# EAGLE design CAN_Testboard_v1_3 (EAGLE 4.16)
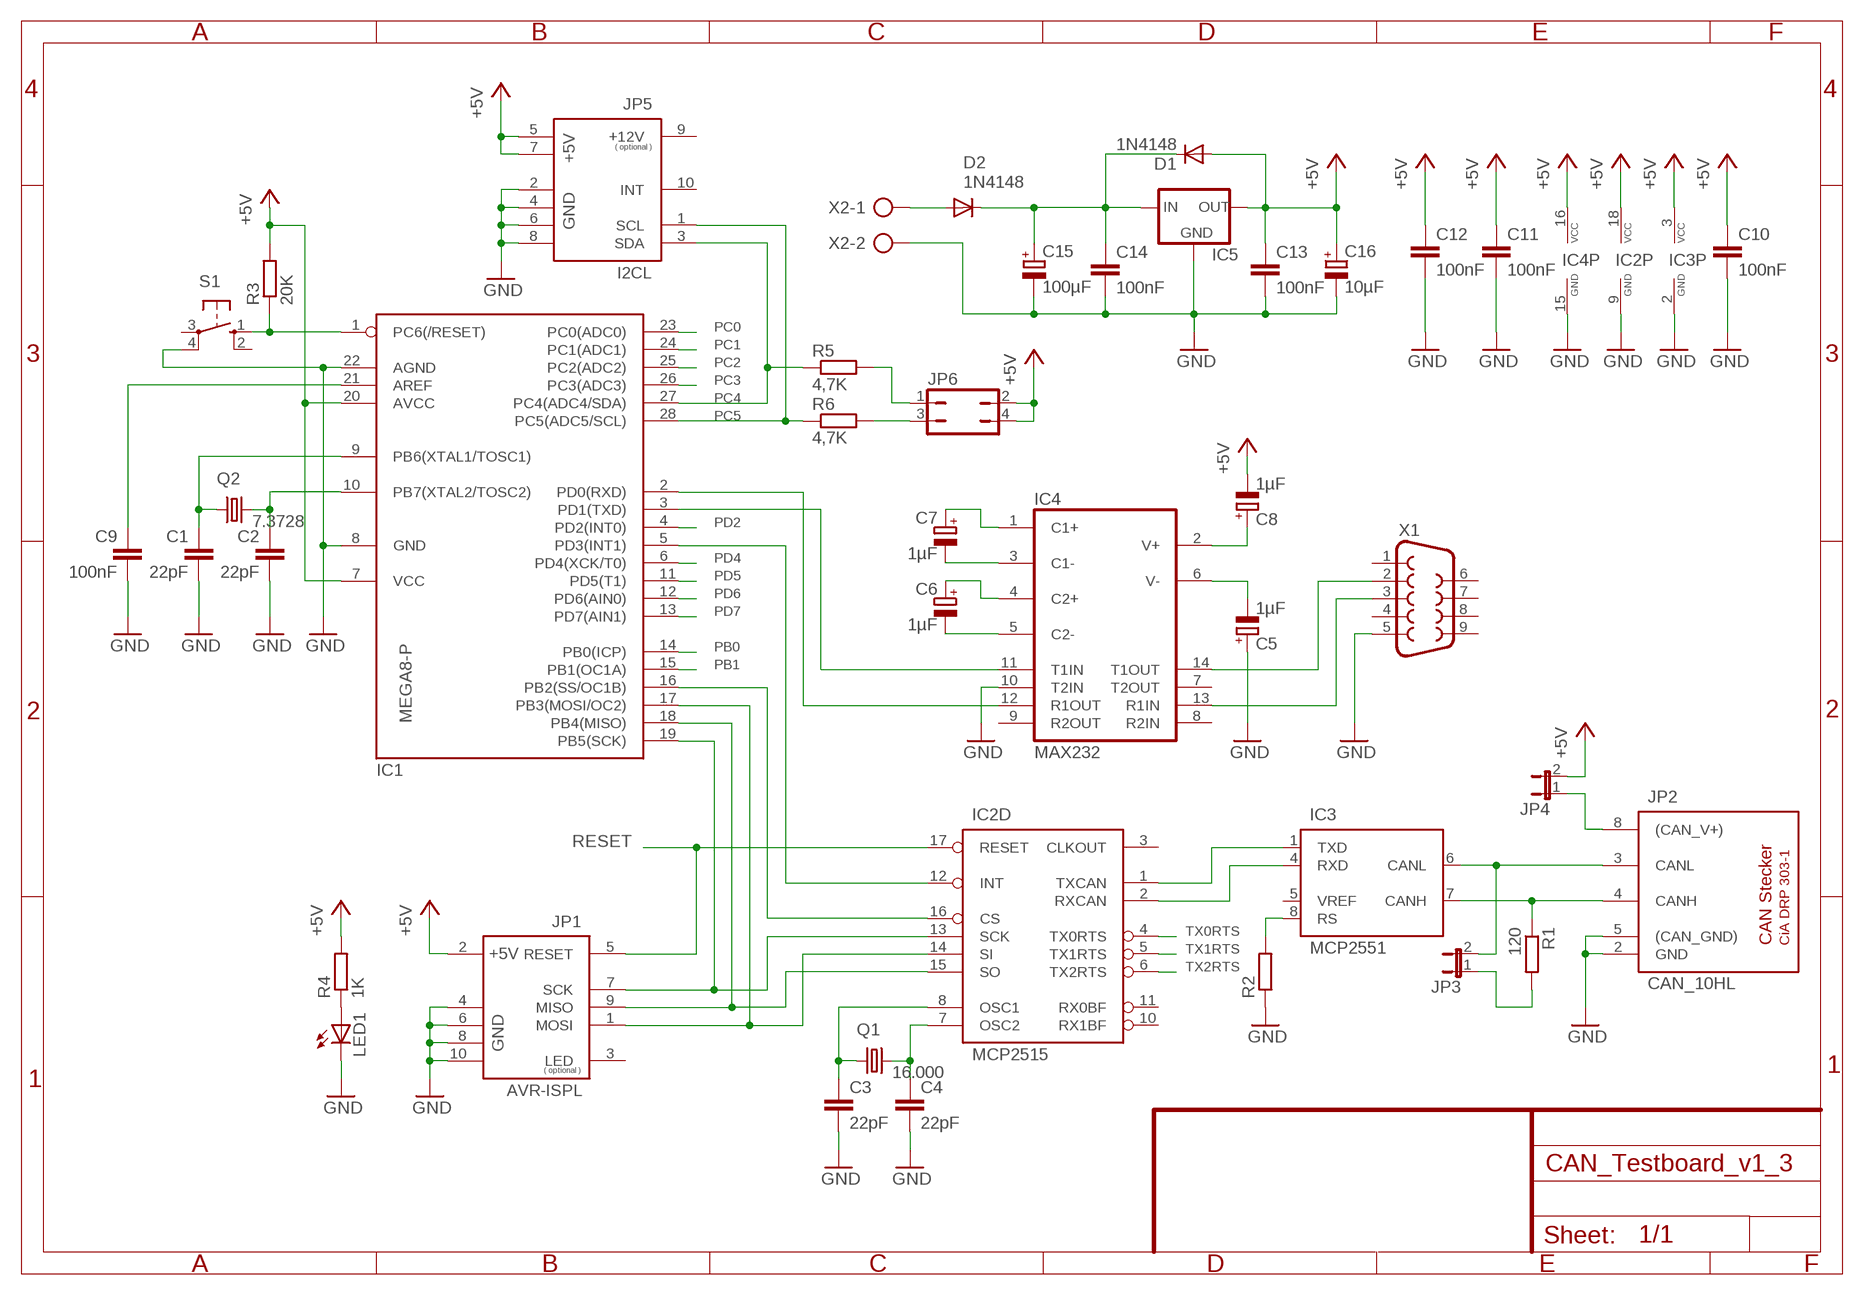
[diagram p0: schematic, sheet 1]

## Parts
C1  22pF  C-EU025-024X044  [C025-024X044]
C2  22pF  C-EU025-024X044  [C025-024X044]
C3  22pF  C-EU025-024X044  [C025-024X044]
C4  22pF  C-EU025-024X044  [C025-024X044]
C5  1µF  CPOL-EUE2.5-5  [E2,5-5]
C6  1µF  CPOL-EUE2.5-5  [E2,5-5]
C7  1µF  CPOL-EUE2.5-5  [E2,5-5]
C8  1µF  CPOL-EUE2.5-5  [E2,5-5]
C9  100nF  C-EU025-024X044  [C025-024X044]
C10  100nF  C-EU025-024X044  [C025-024X044]
C11  100nF  C-EU025-024X044  [C025-024X044]
C12  100nF  C-EU025-024X044  [C025-024X044]
C13  100nF  C-EU025-024X044  [C025-024X044]
C14  100nF  C-EU025-024X044  [C025-024X044]
C15  100µF  CPOL-EUE2.5-7  [E2,5-7]
C16  10µF  CPOL-EUE2.5-5  [E2,5-5]
D1  1N4148  [DO35-10]
D2  1N4148  [DO35-10]
IC1  MEGA8-P  [DIL28-3]
IC2  MCP2515  MCP2515P  [DIL18]
IC3  MCP2551  PCA82C250  [DIL08]
IC4  MAX232  [DIL16]
IC5  78XXL  [78XXL]
JP1  AVR-ISPL  [ML10L]
JP2  CAN_10HL  [ML10L]
JP3  JP1E  [JP1]
JP4  JP1E  [JP1]
JP5  I2CL  [ML10L]
JP6  JP2Q  [JP2Q]
LED1  LED3MM  [LED3MM]
Q1  16.000  CRYTALHC49U-V  [HC49U-V]
Q2  7.3728  CRYTALHC49U-V  [HC49U-V]
R1  120  R-EU_0207/7  [0207/7]
R2  R-EU_0207/7  [0207/7]
R3  20K  R-EU_0207/7  [0207/7]
R4  1K  R-EU_0207/10  [0207/10]
R5  4,7K  R-EU_0207/7  [0207/7]
R6  4,7K  R-EU_0207/7  [0207/7]
S1  10-XX  [B3F-10XX]
X1  F09HP  [F09HP]
X2  AK500/2  [AK500/2]

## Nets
+5V: C8.- C10.1 C11.1 C12.1 C13.1 C16.+ D1.A IC1.7(VCC) IC1.20(AVCC) IC2.18(P:VCC) IC3.3(VCC) IC4.16(VCC) IC5.OUT JP1.2(+5V) JP4.2 JP5.5(+5V) JP5.7(+5V) JP6.2 JP6.4 R3.2 R4.2
CAN_CS: IC1.16(PB2(SS/OC1B)) IC2.16(D:CS)
CAN_INT: IC1.5(PD3(INT1)) IC2.12(D:INT)
GND: C1.2 C2.2 C3.2 C4.2 C5.+ C9.2 C10.2 C11.2 C12.2 C13.2 C14.2 C15.- C16.- IC1.8(GND) IC1.22(AGND) IC2.9(P:GND) IC3.2(GND) IC4.10(T2IN) IC4.15(GND) IC5.GND JP1.4(GND) JP1.6(GND) JP1.8(GND) JP1.10(GND) JP2.2(GND) JP2.5((CAN_GND)) JP5.2(GND) JP5.4(GND) JP5.6(GND) JP5.8(GND) LED1.K(C) R2.1 S1.4(P1) X1.5 X2.2
MISO: IC1.18(PB4(MISO)) IC2.15(D:SO) JP1.9(MISO)
MOSI: IC1.17(PB3(MOSI/OC2)) IC2.14(D:SI) JP1.1(MOSI)
N$1: C6.- IC4.5(C2-)
N$2: C6.+ IC4.4(C2+)
N$3: C7.- IC4.3(C1-)
N$4: C8.+ IC4.2(V+)
N$5: C5.- IC4.6(V-)
N$8: C7.+ IC4.1(C1+)
N$9: C4.1 IC2.7(D:OSC2) Q1.2
N$10: IC2.1(D:TXCAN) IC3.1(TXD)
N$11: IC2.2(D:RXCAN) IC3.4(RXD)
N$12: C3.1 IC2.8(D:OSC1) Q1.1
N$13: C9.1 IC1.21(AREF)
N$17: C2.1 IC1.10(PB7(XTAL2/TOSC2)) Q2.2
N$18: C1.1 IC1.9(PB6(XTAL1/TOSC1)) Q2.1
N$21: IC3.8(RS) R2.2
N$22: IC3.6(CANL) JP2.3(CANL) JP3.2
N$23: IC3.7(CANH) JP2.4(CANH) R1.1
N$24: JP2.8((CAN_V+)) JP4.1
N$25: JP3.1 R1.2
N$44: LED1.A R4.1
N$48: C14.1 C15.+ D1.C D2.C IC5.IN
N$51: D2.A X2.1
N$52: JP6.3 R6.2
N$53: JP6.1 R5.2
PB0: IC1.14(PB0(ICP))
PB1: IC1.15(PB1(OC1A))
PC0: IC1.23(PC0(ADC0))
PC1: IC1.24(PC1(ADC1))
PC2: IC1.25(PC2(ADC2))
PC3: IC1.26(PC3(ADC3))
PC4: IC1.27(PC4(ADC4/SDA)) JP5.3(SDA) R5.1
PC5: IC1.28(PC5(ADC5/SCL)) JP5.1(SCL) R6.1
PD2: IC1.4(PD2(INT0))
PD4: IC1.6(PD4(XCK/T0))
PD5: IC1.11(PD5(T1))
PD6: IC1.12(PD6(AIN0))
PD7: IC1.13(PD7(AIN1))
R_IN: IC4.13(R1IN) X1.3
RESET: IC1.1(PC6(/RESET)) IC2.17(D:RESET) JP1.5(RESET) R3.1 S1.1(S)
RXD: IC1.2(PD0(RXD)) IC4.12(R1OUT)
SCK: IC1.19(PB5(SCK)) IC2.13(D:SCK) JP1.7(SCK)
T_OUT: IC4.14(T1OUT) X1.2
TX0RTS: IC2.4(D:TX0RTS)
TX1RTS: IC2.5(D:TX1RTS)
TX2RTS: IC2.6(D:TX2RTS)
TXD: IC1.3(PD1(TXD)) IC4.11(T1IN)
Unconnected: IC2.3(D:CLKOUT) IC2.10(D:RX1BF) IC2.11(D:RX0BF) IC3.5(VREF) IC4.7(T2OUT) IC4.8(R2IN) IC4.9(R2OUT) JP1.3(LED) JP5.9(+12V) JP5.10(INT) S1.2(S1) S1.3(P) X1.1 X1.4 X1.6 X1.7 X1.8 X1.9

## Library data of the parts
C1-C4 C9-C14 = rcl:C-EU: CAPACITOR, European symbol
C5-C8 C15 C16 = rcl:CPOL-EU: POLARIZED CAPACITOR, European symbol
D1 D2 = diode:1N4148: DIODE
IC1 = avr:MEGA8-P: MICROCONTROLLER 8 Kbytes FLASH 1 kbytes SRAM 512 bytes EEPROM USART 4-channel 10 bit ADC 2-channel 8 bit ADC
IC2 = andereBauteile:MCP2515: MC2515 Stand-Alone CAN Controller With SPI Interface
IC3 = andereBauteile:PCA82C250: PCA82C250 CAN Bustreiber
IC4 = maxim:MAX232: RS232 TRANSEIVER
IC5 = v-reg:78XXL: VOLTAGE REGULATOR
JP1 = roboternetz-definitionen:AVR-ISP: ISP ( In System Programming ) Stecker für AVRs Über diesen Anschluß kann ein AVR mit einem Standard ISP-Kabel direkt an einen Parallelport des PC´s angeschlossen und programmiert werden. Die Belegung des ISP-Anschlusses ist zu dem weit verbreitetet STK200 Programmier Dongle kompatibel. Ein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
JP2 = roboternetz-definitionen:CAN_: CAN Stecker nach CiA DRP 303-1
JP3 JP4 = jumper:JP1E: JUMPER
JP5 = roboternetz-definitionen:I2C: I2C Bus Stecker Ein universeller serieller Bus für Erweiterungen. Der Bus hat den Vorteil das zwei Leitungen ausreichen und keine festen Taktraten und Zyklen beachtet werden müssen. Zahlreichen integrierten Schaltkreise ( wie Porterweiterungen, LCD-Treiber, usw. ) nutzen diesen Bus. Am I2C-Bus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
JP6 = jumper:JP2Q: JUMPER
LED1 = led:LED: LED
Q1 Q2 = crystal:CRYTAL: CRYSTAL
R1-R6 = rcl:R-EU_: RESISTOR, European symbol
S1 = switch-omron:10-XX: OMRON SWITCH
X1 = con-subd:F09: SUB-D
X2 = con-ptr500:AK500/2: CONNECTOR

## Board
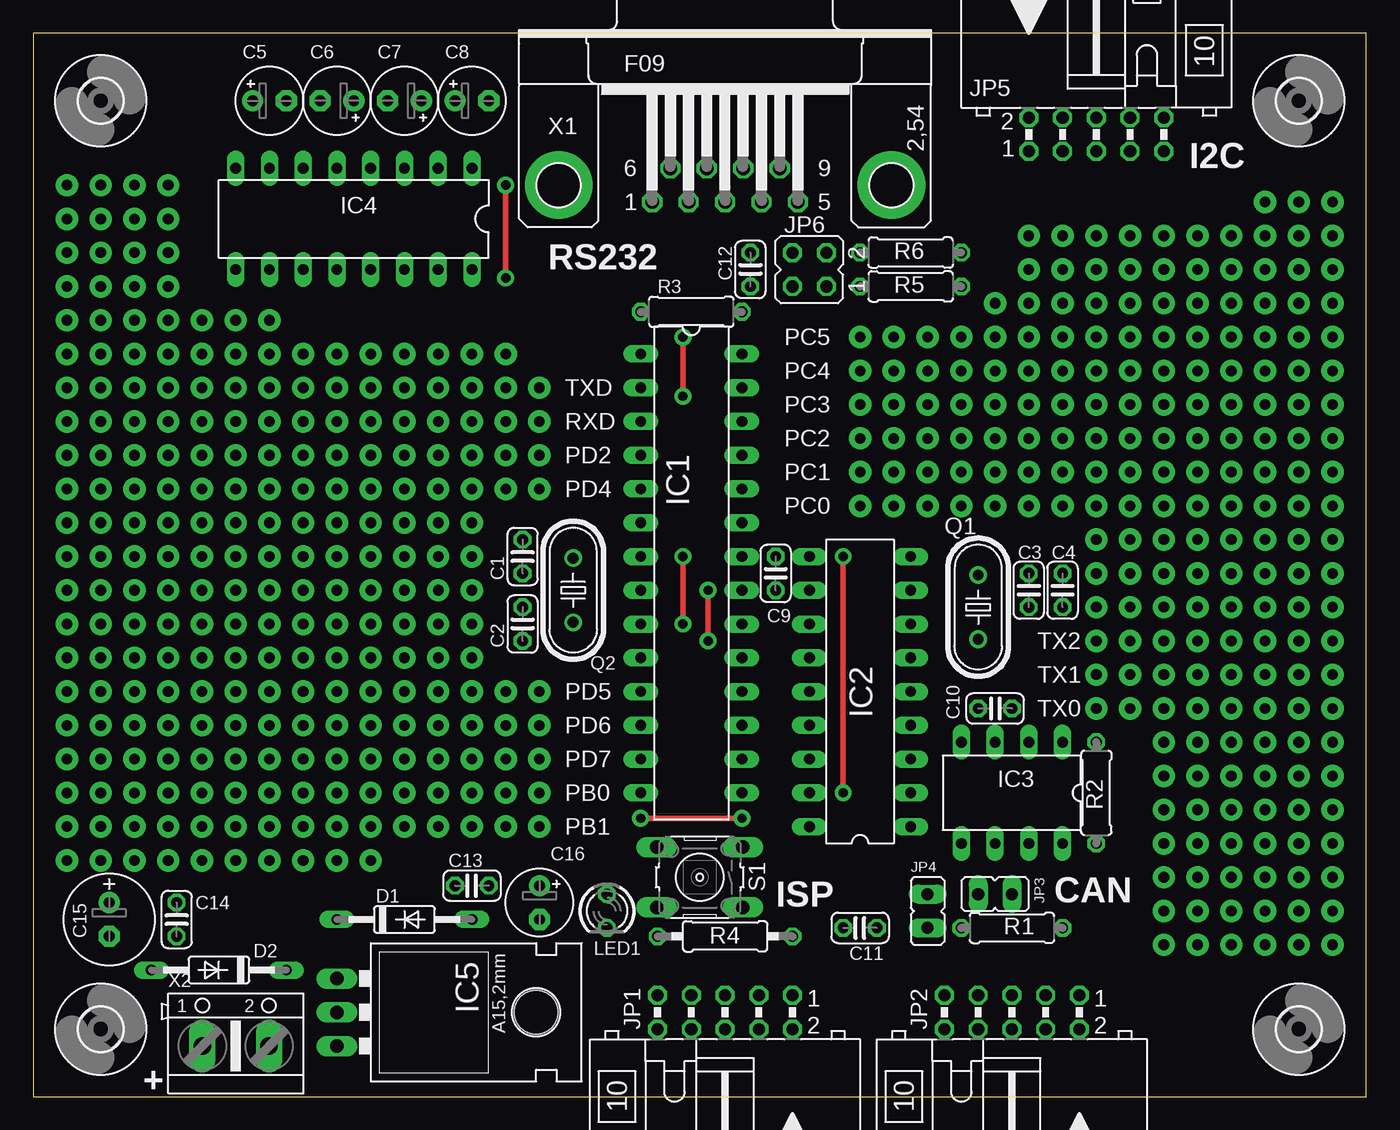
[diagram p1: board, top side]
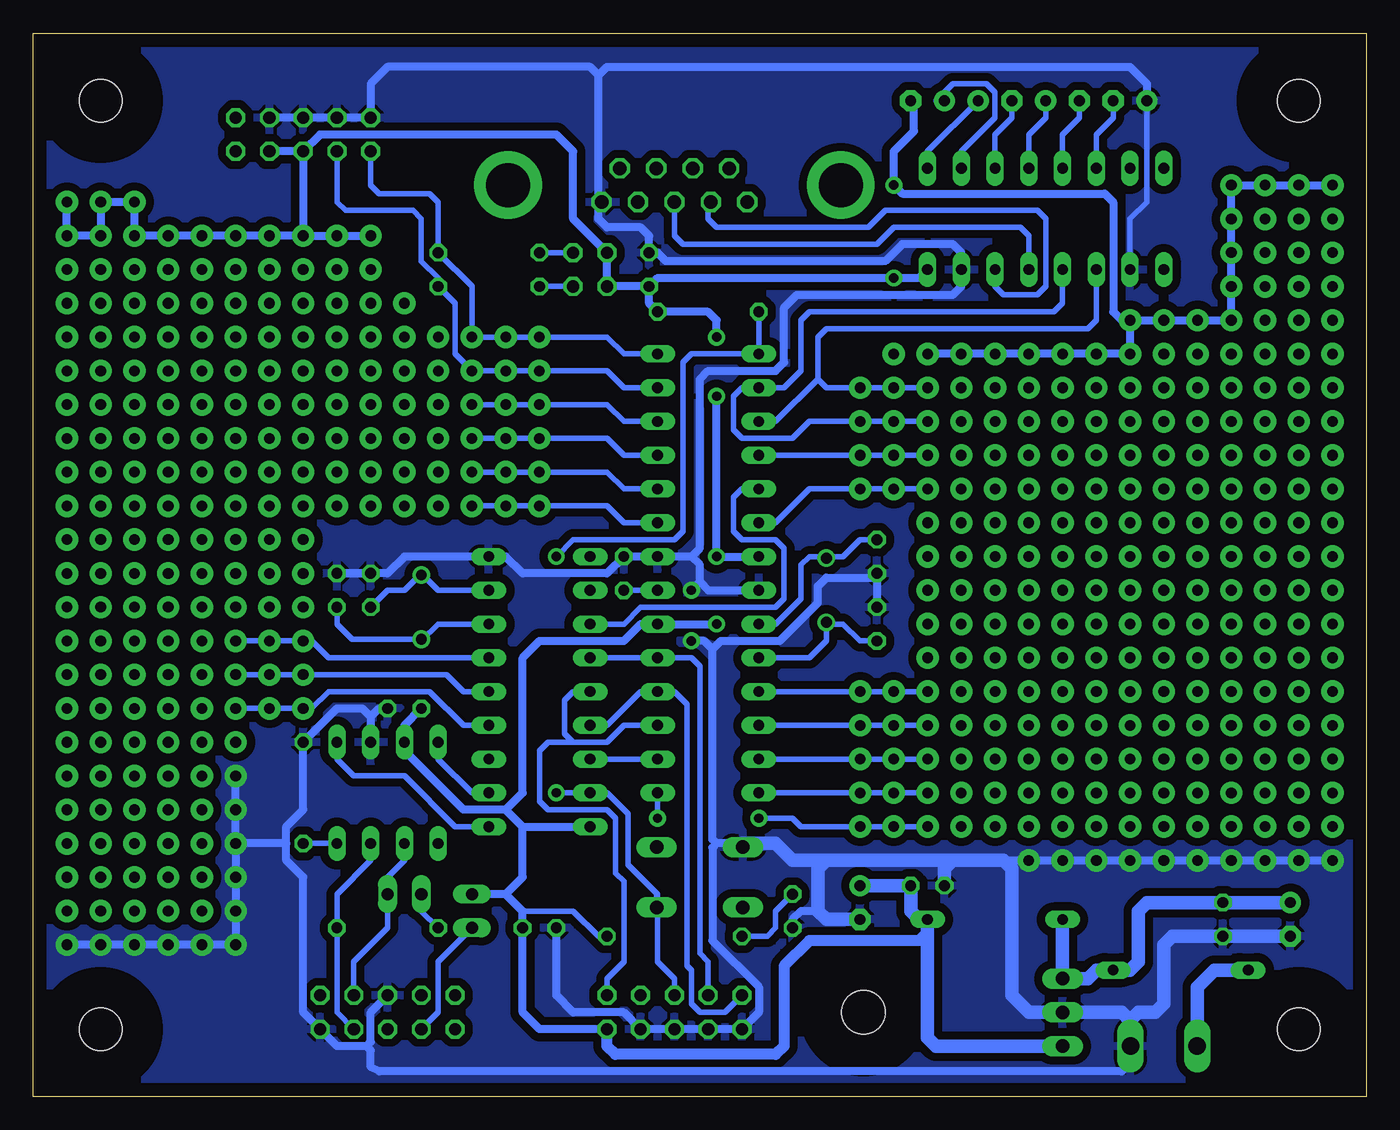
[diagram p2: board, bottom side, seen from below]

Size 100.33 x 80.01 mm. Coordinates in mm from the lower left corner, seen from the top.
Outline: 0,0 100.33,0 100.33,80.01 0,80.01 0,0
Copper layers (1*16): Top 0.035mm / dielectric 1.5mm / Bottom 0.035mm
Design rules "default": minimum track width 10mil, minimum drill 24mil, track to track 8mil, track to pad 8mil, pad to pad 8mil, via to via 8mil, smd to smd 8mil, copper to edge 40mil, drill to drill 8mil, minimum pad ring 10mil, minimum via ring 8mil, stop-mask expansion 4mil, vias tented up to drill 0mil, thermal gap 10mil

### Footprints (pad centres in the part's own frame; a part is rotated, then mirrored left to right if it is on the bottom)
C025-024X044 = drill 0.813 octagon: 1 -1.27,0; 2 1.27,0
E2,5-5 = drill 0.813 pad 1.6 round: + -1.27,0 | drill 0.813 pad 1.6 octagon: - 1.27,0
E2,5-7 = drill 0.813 pad 1.6 round: + -1.27,0 | drill 0.813 pad 1.6 octagon: - 1.27,0
DO35-10 = drill 0.813 long: A 5.08,0; C -5.08,0
DIL28-3 = drill 0.813 long: 1 -16.51,-3.81; 2 -13.97,-3.81; 3 -11.43,-3.81; 4 -8.89,-3.81; 5 -6.35,-3.81; 6 -3.81,-3.81; 7 -1.27,-3.81; 8 1.27,-3.81; 9 3.81,-3.81; 10 6.35,-3.81; 11 8.89,-3.81; 12 11.43,-3.81; 13 13.97,-3.81; 14 16.51,-3.81; 15 16.51,3.81; 16 13.97,3.81; 17 11.43,3.81; 18 8.89,3.81; 19 6.35,3.81; 20 3.81,3.81; 21 1.27,3.81; 22 -1.27,3.81; 23 -3.81,3.81; 24 -6.35,3.81; 25 -8.89,3.81; 26 -11.43,3.81; 27 -13.97,3.81; 28 -16.51,3.81
DIL18 = drill 0.813 long: 1 -10.16,-3.81; 2 -7.62,-3.81; 3 -5.08,-3.81; 4 -2.54,-3.81; 5 0,-3.81; 6 2.54,-3.81; 7 5.08,-3.81; 8 7.62,-3.81; 9 10.16,-3.81; 10 10.16,3.81; 11 7.62,3.81; 12 5.08,3.81; 13 2.54,3.81; 14 0,3.81; 15 -2.54,3.81; 16 -5.08,3.81; 17 -7.62,3.81; 18 -10.16,3.81
DIL08 = drill 0.813 long: 1 -3.81,-3.81; 2 -1.27,-3.81; 3 1.27,-3.81; 4 3.81,-3.81; 5 3.81,3.81; 6 1.27,3.81; 7 -1.27,3.81; 8 -3.81,3.81
DIL16 = drill 0.813 long: 1 -8.89,-3.81; 2 -6.35,-3.81; 3 -3.81,-3.81; 4 -1.27,-3.81; 5 1.27,-3.81; 6 3.81,-3.81; 7 6.35,-3.81; 8 8.89,-3.81; 9 8.89,3.81; 10 6.35,3.81; 11 3.81,3.81; 12 1.27,3.81; 13 -1.27,3.81; 14 -3.81,3.81; 15 -6.35,3.81; 16 -8.89,3.81
78XXL = drill 1.016 long: GND 0,-3.81; IN -2.54,-3.81; OUT 2.54,-3.81 | hole 3.302: 0,11.176
ML10L = drill 0.914 octagon: 1 -5.08,-1.27; 2 -5.08,1.27; 3 -2.54,-1.27; 4 -2.54,1.27; 5 0,-1.27; 6 0,1.27; 7 2.54,-1.27; 8 2.54,1.27; 9 5.08,-1.27; 10 5.08,1.27
JP1 = drill 0.914 long: 1 0,-1.27; 2 0,1.27
JP2Q = drill 0.914 octagon: 1 -1.27,-1.27; 2 -1.27,1.27; 3 1.27,-1.27; 4 1.27,1.27
LED3MM = drill 0.813 octagon: A -1.27,0; K 1.27,0
HC49U-V = drill 0.813 round: 1 -2.413,0; 2 2.413,0
0207/7 = drill 0.813 octagon: 1 -3.81,0; 2 3.81,0
0207/10 = drill 0.813 octagon: 1 -5.08,0; 2 5.08,0
B3F-10XX = drill 1.016 long: 1 -3.251,2.261; 2 3.251,2.261; 3 -3.251,-2.261; 4 3.251,-2.261
3,2 = hole 3.2: 0,0
F09HP = drill 1.016 octagon: 1 -5.486,-1.27; 2 -2.743,-1.27; 3 0,-1.27; 4 2.743,-1.27; 5 5.486,-1.27; 6 -4.115,1.27; 7 -1.372,1.27; 8 1.372,1.27; 9 4.115,1.27 | drill 3.302 pad 5.08 round: G1 -12.522,0; G2 12.522,0
AK500/2 = drill 1.321 long: 1 -2.515,0; 2 2.515,0

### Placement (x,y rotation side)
C1  36.83,40.64 270 top
C2  36.83,35.56 90 top
C3  74.93,38.1 90 top
C4  77.47,38.1 90 top
C5  17.78,74.93 0 top
C6  22.86,74.93 180 top
C7  27.94,74.93 180 top
C8  33.02,74.93 0 top
C9  55.88,39.37 90 top
C10  72.39,29.21 0 top
C11  62.23,12.7 180 top
C12  53.98,62.23 90 top
C13  33.02,15.88 180 top
C14  10.79,13.34 270 top
C15  5.71,13.34 270 top
C16  38.1,14.61 270 top
D1  27.94,13.34 0 top
D2  13.97,9.53 180 top
IC1  49.53,39.37 270 top
IC2  62.23,30.48 90 top
IC3  73.66,22.86 180 top
IC4  24.13,66.04 180 top
IC5  26.67,6.35 270 top
JP1  52.07,6.35 180 top
JP2  73.66,6.35 180 top
JP3  72.39,15.24 270 top
JP4  67.31,13.97 0 top
JP5  80.01,72.39 0 top
JP6  58.42,62.23 90 top
LED1  43.18,13.97 270 top
Q1  71.12,36.83 270 top
Q2  40.64,38.1 270 top
R1  73.66,12.7 180 top
R2  80.01,22.86 270 top
R3  49.53,59.05 0 top
R4  52.07,12.06 0 top
R5  66.04,60.96 180 top
R6  66.04,63.5 180 top
S1  50.16,16.51 180 top
U$1  [3,2]  5.08,5.08 0 top
U$2  [3,2]  95.25,5.08 0 top
U$3  [3,2]  95.25,74.93 0 top
U$4  [3,2]  5.08,74.93 0 top
X1  52.07,68.58 0 top
X2  15.24,3.81 0 top

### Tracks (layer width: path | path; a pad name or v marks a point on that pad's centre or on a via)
+5V  (via drill 0.7 pad 1.27, 0.8 pad 1.68)
  Top 0.406: v48.9,35.56 v48.9,40.64 | v35.56,61.59 v35.56,68.58 | v48.9,52.7 v48.9,57.15
  Bottom 0.406: R4.2 57.78,12.06 59.69,13.97 63.5,13.97
  Bottom 0.61: 64.77,21.59 67.94,21.59 72.39,26.04 IC3.3 72.39,27.94 C10.1 | 63.5,20.32 64.77,21.59 | 63.5,20.32 IC2.18 | JP1.2 62.23,5.08 63.5,6.35 C11.1 63.5,13.97 64.77,15.24 | 64.77,15.24 JP4.2 | 64.77,15.24 63.5,16.51 63.5,20.32 | v48.9,35.56 IC1.20 54.61,35.56 55.88,34.29 62.23,34.29 63.5,33.02 63.5,22.86 64.77,21.59 | IC1.7 v48.9,40.64 v48.9,52.7 | C8.- 34.04,74.68 34.04,72.64 35.56,71.12 v35.56,68.58 34.92,67.94 19.68,67.94 19.05,67.31 19.05,59.05 18.41,58.42 v17.78,58.42 | IC4.16 33.66,61.59 v35.56,61.59 53.34,61.59 C12.1 | v48.9,57.15 48.9,58.42 49.53,59.05 R3.2 53.98,59.69 C12.1 | v17.78,58.42 v15.24,58.42 v12.7,58.42 v10.16,58.42 v10.16,60.96 v10.16,63.5 v10.16,66.04 v10.16,68.58 v7.62,68.58 v5.08,68.58 v2.54,68.58 | JP5.5 JP5.7 | JP5.5 78.74,72.39 60.96,72.39 59.69,71.12 59.69,66.04 JP6.4 JP6.2 C12.1 | JP5.5 v80.01,64.77 | v80.01,64.77 v77.47,64.77 v74.93,64.77 | v80.01,64.77 v82.55,64.77 v85.09,64.77 v87.63,64.77 v90.17,64.77 v92.71,64.77 v92.71,67.31 v95.25,67.31 v95.25,64.77 v97.79,64.77 v97.79,67.31 | v17.78,58.42 v17.78,55.88 v20.32,55.88 v22.86,55.88 v25.4,55.88 v27.94,55.88 v30.48,55.88 v33.02,55.88
  Bottom 0.813: JP1.2 57.15,3.81 56.52,3.17 44.45,3.17 43.81,3.81 43.81,9.84 41.91,11.75 33.66,11.75 33.02,12.38
  Bottom 1.016: IC5.OUT 32.38,3.81 33.02,4.45 33.02,12.38 D1.A 33.66,13.34 34.29,13.97 C13.1 C16.+
CAN_CS
  Bottom 0.406: IC1.16 IC2.16
CAN_INT
  Bottom 0.406: IC2.12 55.88,35.56 54.61,36.83 44.45,36.83 43.81,37.47 43.81,41.27 44.45,41.91 46.99,41.91 47.62,42.55 47.62,45.09 46.99,45.72 IC1.5
GND  (via drill 0.7 pad 1.27, 0.8 pad 1.68)
  Top 0.406: v50.8,34.29 v50.8,38.1
  Bottom 0.406: IC4.10 17.78,66.04 16.51,67.31 C5.+ | 57.78,67.31 X1.5
  Bottom 0.61: C3.2 C4.2 73.66,39.37 72.39,40.64 IC2.9 64.77,40.64 63.5,39.37 57.15,39.37 C9.2 IC1.22 50.8,40.64 | JP2.5 74.93,6.35 74.93,4.13 75.25,3.81 | 75.25,3.81 77.47,3.81 JP2.2 80.01,6.35 80.01,16.51 81.28,17.78 81.28,19.05 | 81.28,19.05 81.28,20.32 80.01,21.59 R2.1 77.47,29.21 75.56,29.21 74.93,28.57 | IC1.8 49.53,38.1 50.16,38.73 | 50.16,38.73 50.16,40.01 50.8,40.64 | C2.2 C1.2 37.15,39.05 40.64,39.05 41.27,38.42 41.27,37.15 44.13,34.29 48.58,34.29 49.21,33.66 | C11.2 60.96,7.62 59.69,6.35 55.88,6.35 JP1.4 JP1.6 JP1.8 JP1.10 45.72,6.35 45.72,8.26 49.21,11.75 49.21,18.73 48.9,19.05 | 50.8,40.64 50.16,41.27 50.16,53.98 49.53,54.61 44.45,54.61 43.81,55.24 43.81,59.37 42.86,60.33 31.11,60.33 30.48,60.96 IC4.15 30.48,63.5 31.11,64.14 34.92,64.14 36.2,62.87 52.7,62.87 53.34,63.5 C12.2 53.98,64.77 54.61,65.41 57.15,65.41 57.78,66.04 57.78,67.31 57.78,76.83 | C5.+ 16.51,76.2 17.78,77.47 57.15,77.47 57.78,76.83 | 49.21,33.66 49.85,34.29 v50.8,34.29 | v50.8,38.1 50.16,38.73 | v97.79,11.43 v95.25,11.43 v92.71,11.43 v90.17,11.43 v87.63,11.43 v85.09,11.43 v85.09,13.97 v85.09,16.51 v85.09,19.05 | v2.54,17.78 v5.08,17.78 v7.62,17.78 v10.16,17.78 v12.7,17.78 v15.24,17.78 v17.78,17.78 v20.32,17.78 v22.86,17.78 27.3,17.78 | 57.78,76.83 58.42,77.47 73.66,77.47 74.93,76.2 JP5.2 JP5.4 JP5.6 JP5.8 | S1.4 46.91,19.13 46.99,19.05 48.9,19.05 | 49.21,33.66 49.21,19.37 48.9,19.05 | v85.09,19.05 v85.09,21.59 v85.09,24.13 | 81.28,19.05 v85.09,19.05 | 74.93,28.57 74.3,29.21 C10.2 | 74.93,28.57 IC3.2 | 75.25,3.81 74.93,3.49 74.93,2.22 74.3,1.91 18.41,1.91 17.78,2.54 17.78,3.81
  Bottom 0.61: LED1.K 43.18,13.34 42.55,13.97 41.27,13.97
  Bottom 1.016: 31.11,17.78 27.3,17.78 26.67,17.14 26.67,7.62 25.4,6.35 IC5.GND 18.41,6.35 17.78,5.71 | 31.11,17.78 40.64,17.78 | X2.2 17.78,3.81 17.78,5.71 | C15.- C14.2 14.61,12.06 15.24,11.43 15.24,6.99 15.88,6.35 17.14,6.35 17.78,5.71 | C13.2 31.75,17.14 31.11,17.78 | C16.- 40.64,13.34 41.27,13.97 41.27,17.14 40.64,17.78 | 40.64,17.78 43.18,17.78 44.45,19.05 46.99,19.05 46.91,18.97 S1.4
  other vias: 25.4,17.78
  pour Bottom (isolate 0.61): -1.27,81.28 101.6,81.28 101.6,-1.27 -1.27,-1.27
MISO
  Bottom 0.406: IC2.15 57.15,27.94 54.61,30.48 IC1.18 52.07,30.48 51.12,29.53 51.12,9.84 50.8,9.53 50.8,6.99 50.16,6.35 48.26,6.35 JP1.9
MOSI
  Bottom 0.406: JP1.1 57.15,8.89 55.88,10.16 55.88,16.19 56.52,16.83 56.52,20.95 57.15,21.59 61.59,21.59 62.23,22.23 62.23,26.04 61.59,26.67 59.69,26.67 | IC1.17 55.88,27.94 57.15,26.67 59.69,26.67 | 59.69,26.67 60.33,27.3 60.33,29.84 59.69,30.48 IC2.14
N$1
  Bottom 0.406: IC4.5 22.86,72.39 21.59,73.66 C6.-
N$2
  Bottom 0.406: IC4.4 25.4,72.39 24.13,73.66 C6.+
N$3
  Bottom 0.406: IC4.3 27.94,72.39 26.67,73.66 C7.-
N$4
  Bottom 0.406: IC4.2 30.48,71.12 27.94,73.66 27.94,75.56 28.57,76.2 31.11,76.2 32.38,74.93 C8.+
N$5
  Bottom 0.406: IC4.6 20.32,72.39 19.05,73.66 C5.-
N$8
  Bottom 0.406: IC4.1 33.02,71.12 C7.+
N$9
  Bottom 0.406: IC2.7 69.85,35.56 71.12,34.29 Q1.2 76.33,34.42 77.47,35.56 C4.1
N$10
  Bottom 0.406: IC2.1 68.58,20.32 72.39,24.13 76.2,24.13 77.47,25.4 IC3.1
N$11
  Bottom 0.406: IC3.4 69.85,25.4 67.31,22.86 IC2.2
N$12
  Bottom 0.406: IC2.8 69.85,38.1 71.12,39.37 Q1.1 71.25,39.24 72.39,38.1 73.66,38.1 C3.1
N$13
  Bottom 0.406: IC1.21 C9.1
N$17
  Bottom 0.406: 40.64,35.56 40.64,34.29 41.91,33.02 IC1.10 | C2.1 38.1,34.29 39.37,35.56 40.64,35.56 | 40.64,35.56 Q2.2
N$18
  Bottom 0.406: C1.1 38.1,41.91 39.37,40.64 40.64,40.64 | 40.64,40.64 Q2.1 | 40.64,40.64 41.91,40.64 42.55,40.01 42.55,37.47 44.45,35.56 IC1.9
N$21
  Bottom 0.406: IC3.8 R2.2
N$22
  Bottom 0.406: IC3.6 72.39,17.78 73.66,16.51 JP3.2 73.66,12.7 76.2,10.16 JP2.3
N$23
  Bottom 0.406: JP2.4 77.47,6.35 R1.1 77.47,15.24 74.93,17.78 IC3.7
N$24
  Bottom 0.406: JP2.8 69.85,6.35 69.85,10.16 JP4.1
N$25
  Bottom 0.406: R1.2 71.12,13.97 JP3.1
N$29  (via drill 0.8 pad 1.68)
  other vias: 20.32,48.26
N$30  (via drill 0.8 pad 1.68)
  other vias: 22.86,48.26
N$31  (via drill 0.8 pad 1.68)
  other vias: 25.4,48.26
N$32  (via drill 0.8 pad 1.68)
  other vias: 25.4,45.72
N$33  (via drill 0.8 pad 1.68)
  other vias: 22.86,45.72
N$34  (via drill 0.8 pad 1.68)
  other vias: 20.32,45.72
N$35  (via drill 0.8 pad 1.68)
  other vias: 20.32,43.18
N$36  (via drill 0.8 pad 1.68)
  other vias: 22.86,43.18
N$37  (via drill 0.8 pad 1.68)
  other vias: 25.4,43.18
N$38  (via drill 0.8 pad 1.68)
  other vias: 25.4,50.8
N$39  (via drill 0.8 pad 1.68)
  other vias: 22.86,50.8
N$40  (via drill 0.8 pad 1.68)
  other vias: 20.32,50.8
N$41  (via drill 0.8 pad 1.68)
  other vias: 20.32,53.34
N$42  (via drill 0.8 pad 1.68)
  other vias: 22.86,53.34
N$43  (via drill 0.8 pad 1.68)
  other vias: 25.4,53.34
N$44
  Bottom 0.406: LED1.A 44.45,13.97 44.45,12.7 45.09,12.06 R4.1
N$45  (via drill 0.8 pad 1.68)
  other vias: 77.47,62.23
N$46  (via drill 0.8 pad 1.68)
  other vias: 80.01,62.23
N$47  (via drill 0.8 pad 1.68)
  other vias: 82.55,62.23
N$48
  Bottom 1.016: D1.C IC5.IN 20.95,8.89 20.32,9.53 D2.C 17.78,9.53 17.14,10.16 17.14,13.97 16.51,14.61 C14.1 C15.+
N$49  (via drill 0.8 pad 1.68)
  other vias: 85.09,62.23
N$50  (via drill 0.8 pad 1.68)
  other vias: 74.93,62.23
N$51
  Bottom 1.016: X2.1 12.72,8.23 11.43,9.53 D2.A
N$52
  Bottom 0.406: JP6.3 R6.2
N$53
  Bottom 0.406: JP6.1 R5.2
N$54  (via drill 0.8 pad 1.68)
  other vias: 33.02,43.18
N$59  (via drill 0.8 pad 1.68)
  other vias: 27.94,48.26
N$60  (via drill 0.8 pad 1.68)
  other vias: 30.48,48.26
N$61  (via drill 0.8 pad 1.68)
  other vias: 69.85,54.61
N$62  (via drill 0.8 pad 1.68)
  other vias: 69.85,57.15
N$63  (via drill 0.8 pad 1.68)
  other vias: 30.48,45.72
N$64  (via drill 0.8 pad 1.68)
  other vias: 27.94,45.72
N$65  (via drill 0.8 pad 1.68)
  other vias: 27.94,43.18
N$66  (via drill 0.8 pad 1.68)
  other vias: 30.48,43.18
N$67  (via drill 0.8 pad 1.68)
  other vias: 85.09,26.67
N$69  (via drill 0.8 pad 1.68)
  other vias: 30.48,50.8
N$70  (via drill 0.8 pad 1.68)
  other vias: 27.94,50.8
N$71  (via drill 0.8 pad 1.68)
  other vias: 27.94,53.34
N$72  (via drill 0.8 pad 1.68)
  other vias: 30.48,53.34
N$74  (via drill 0.8 pad 1.68)
  other vias: 12.7,48.26
N$75  (via drill 0.8 pad 1.68)
  other vias: 15.24,48.26
N$76  (via drill 0.8 pad 1.68)
  other vias: 17.78,48.26
N$77  (via drill 0.8 pad 1.68)
  other vias: 17.78,45.72
N$78  (via drill 0.8 pad 1.68)
  other vias: 15.24,45.72
N$79  (via drill 0.8 pad 1.68)
  other vias: 12.7,45.72
N$80  (via drill 0.8 pad 1.68)
  other vias: 12.7,43.18
N$81  (via drill 0.8 pad 1.68)
  other vias: 15.24,43.18
N$82  (via drill 0.8 pad 1.68)
  other vias: 17.78,43.18
N$83  (via drill 0.8 pad 1.68)
  other vias: 17.78,50.8
N$84  (via drill 0.8 pad 1.68)
  other vias: 15.24,50.8
N$85  (via drill 0.8 pad 1.68)
  other vias: 12.7,50.8
N$86  (via drill 0.8 pad 1.68)
  other vias: 12.7,53.34
N$87  (via drill 0.8 pad 1.68)
  other vias: 15.24,53.34
N$88  (via drill 0.8 pad 1.68)
  other vias: 17.78,53.34
N$89  (via drill 0.8 pad 1.68)
  other vias: 5.08,48.26
N$90  (via drill 0.8 pad 1.68)
  other vias: 7.62,48.26
N$91  (via drill 0.8 pad 1.68)
  other vias: 10.16,48.26
N$92  (via drill 0.8 pad 1.68)
  other vias: 10.16,45.72
N$93  (via drill 0.8 pad 1.68)
  other vias: 7.62,45.72
N$94  (via drill 0.8 pad 1.68)
  other vias: 5.08,45.72
N$95  (via drill 0.8 pad 1.68)
  other vias: 5.08,43.18
N$96  (via drill 0.8 pad 1.68)
  other vias: 7.62,43.18
N$97  (via drill 0.8 pad 1.68)
  other vias: 10.16,43.18
N$98  (via drill 0.8 pad 1.68)
  other vias: 10.16,50.8
N$99  (via drill 0.8 pad 1.68)
  other vias: 7.62,50.8
N$100  (via drill 0.8 pad 1.68)
  other vias: 5.08,50.8
N$101  (via drill 0.8 pad 1.68)
  other vias: 5.08,53.34
N$102  (via drill 0.8 pad 1.68)
  other vias: 7.62,53.34
N$103  (via drill 0.8 pad 1.68)
  other vias: 10.16,53.34
N$104  (via drill 0.8 pad 1.68)
  other vias: 2.54,48.26
N$105  (via drill 0.8 pad 1.68)
  other vias: 2.54,45.72
N$106  (via drill 0.8 pad 1.68)
  other vias: 2.54,43.18
N$107  (via drill 0.8 pad 1.68)
  other vias: 2.54,50.8
N$108  (via drill 0.8 pad 1.68)
  other vias: 2.54,53.34
N$109  (via drill 0.8 pad 1.68)
  other vias: 20.32,35.56
N$110  (via drill 0.8 pad 1.68)
  other vias: 22.86,35.56
N$111  (via drill 0.8 pad 1.68)
  other vias: 25.4,35.56
N$112  (via drill 0.8 pad 1.68)
  other vias: 25.4,33.02
N$113  (via drill 0.8 pad 1.68)
  other vias: 22.86,33.02
N$114  (via drill 0.8 pad 1.68)
  other vias: 20.32,33.02
N$115  (via drill 0.8 pad 1.68)
  other vias: 20.32,30.48
N$116  (via drill 0.8 pad 1.68)
  other vias: 22.86,30.48
N$117  (via drill 0.8 pad 1.68)
  other vias: 25.4,30.48
N$118  (via drill 0.8 pad 1.68)
  other vias: 25.4,38.1
N$119  (via drill 0.8 pad 1.68)
  other vias: 22.86,38.1
N$120  (via drill 0.8 pad 1.68)
  other vias: 20.32,38.1
N$121  (via drill 0.8 pad 1.68)
  other vias: 20.32,40.64
N$122  (via drill 0.8 pad 1.68)
  other vias: 22.86,40.64
N$123  (via drill 0.8 pad 1.68)
  other vias: 25.4,40.64
N$124  (via drill 0.8 pad 1.68)
  other vias: 27.94,35.56
N$125  (via drill 0.8 pad 1.68)
  other vias: 30.48,35.56
N$126  (via drill 0.8 pad 1.68)
  other vias: 33.02,35.56
N$127  (via drill 0.8 pad 1.68)
  other vias: 33.02,33.02
N$128  (via drill 0.8 pad 1.68)
  other vias: 30.48,33.02
N$129  (via drill 0.8 pad 1.68)
  other vias: 27.94,33.02
N$130  (via drill 0.8 pad 1.68)
  other vias: 27.94,30.48
N$131  (via drill 0.8 pad 1.68)
  other vias: 30.48,30.48
N$133  (via drill 0.8 pad 1.68)
  other vias: 33.02,38.1
N$134  (via drill 0.8 pad 1.68)
  other vias: 30.48,38.1
N$135  (via drill 0.8 pad 1.68)
  other vias: 27.94,38.1
N$136  (via drill 0.8 pad 1.68)
  other vias: 27.94,40.64
N$137  (via drill 0.8 pad 1.68)
  other vias: 30.48,40.64
N$138  (via drill 0.8 pad 1.68)
  other vias: 33.02,40.64
N$139  (via drill 0.8 pad 1.68)
  other vias: 12.7,35.56
N$140  (via drill 0.8 pad 1.68)
  other vias: 15.24,35.56
N$141  (via drill 0.8 pad 1.68)
  other vias: 17.78,35.56
N$142  (via drill 0.8 pad 1.68)
  other vias: 17.78,33.02
N$143  (via drill 0.8 pad 1.68)
  other vias: 15.24,33.02
N$144  (via drill 0.8 pad 1.68)
  other vias: 12.7,33.02
N$145  (via drill 0.8 pad 1.68)
  other vias: 12.7,30.48
N$146  (via drill 0.8 pad 1.68)
  other vias: 15.24,30.48
N$147  (via drill 0.8 pad 1.68)
  other vias: 17.78,30.48
N$148  (via drill 0.8 pad 1.68)
  other vias: 17.78,38.1
N$149  (via drill 0.8 pad 1.68)
  other vias: 15.24,38.1
N$150  (via drill 0.8 pad 1.68)
  other vias: 12.7,38.1
N$151  (via drill 0.8 pad 1.68)
  other vias: 12.7,40.64
N$152  (via drill 0.8 pad 1.68)
  other vias: 15.24,40.64
N$153  (via drill 0.8 pad 1.68)
  other vias: 17.78,40.64
N$154  (via drill 0.8 pad 1.68)
  other vias: 5.08,35.56
N$155  (via drill 0.8 pad 1.68)
  other vias: 7.62,35.56
N$156  (via drill 0.8 pad 1.68)
  other vias: 10.16,35.56
N$157  (via drill 0.8 pad 1.68)
  other vias: 10.16,33.02
N$158  (via drill 0.8 pad 1.68)
  other vias: 7.62,33.02
N$159  (via drill 0.8 pad 1.68)
  other vias: 5.08,33.02
N$160  (via drill 0.8 pad 1.68)
  other vias: 5.08,30.48
N$161  (via drill 0.8 pad 1.68)
  other vias: 7.62,30.48
N$162  (via drill 0.8 pad 1.68)
  other vias: 10.16,30.48
N$163  (via drill 0.8 pad 1.68)
  other vias: 10.16,38.1
N$164  (via drill 0.8 pad 1.68)
  other vias: 7.62,38.1
N$165  (via drill 0.8 pad 1.68)
  other vias: 5.08,38.1
N$166  (via drill 0.8 pad 1.68)
  other vias: 5.08,40.64
N$167  (via drill 0.8 pad 1.68)
  other vias: 7.62,40.64
N$168  (via drill 0.8 pad 1.68)
  other vias: 10.16,40.64
N$169  (via drill 0.8 pad 1.68)
  other vias: 2.54,35.56
N$170  (via drill 0.8 pad 1.68)
  other vias: 2.54,33.02
N$171  (via drill 0.8 pad 1.68)
  other vias: 2.54,30.48
N$172  (via drill 0.8 pad 1.68)
  other vias: 2.54,38.1
N$173  (via drill 0.8 pad 1.68)
  other vias: 2.54,40.64
N$174  (via drill 0.8 pad 1.68)
  other vias: 20.32,22.86
N$175  (via drill 0.8 pad 1.68)
  other vias: 22.86,22.86
N$176  (via drill 0.8 pad 1.68)
  other vias: 25.4,22.86
N$177  (via drill 0.8 pad 1.68)
  other vias: 25.4,20.32
N$178  (via drill 0.8 pad 1.68)
  other vias: 22.86,20.32
N$179  (via drill 0.8 pad 1.68)
  other vias: 20.32,20.32
N$180  (via drill 0.8 pad 1.68)
  other vias: 87.63,24.13
N$181  (via drill 0.8 pad 1.68)
  other vias: 90.17,24.13
N$183  (via drill 0.8 pad 1.68)
  other vias: 25.4,25.4
N$184  (via drill 0.8 pad 1.68)
  other vias: 22.86,25.4
N$185  (via drill 0.8 pad 1.68)
  other vias: 20.32,25.4
N$186  (via drill 0.8 pad 1.68)
  other vias: 20.32,27.94
N$187  (via drill 0.8 pad 1.68)
  other vias: 22.86,27.94
N$188  (via drill 0.8 pad 1.68)
  other vias: 25.4,27.94
N$189  (via drill 0.8 pad 1.68)
  other vias: 27.94,22.86
N$190  (via drill 0.8 pad 1.68)
  other vias: 30.48,22.86
N$191  (via drill 0.8 pad 1.68)
  other vias: 80.01,39.37
N$192  (via drill 0.8 pad 1.68)
  other vias: 80.01,36.83
N$193  (via drill 0.8 pad 1.68)
  other vias: 30.48,20.32
N$194  (via drill 0.8 pad 1.68)
  other vias: 27.94,20.32
N$199  (via drill 0.8 pad 1.68)
  other vias: 30.48,25.4
N$200  (via drill 0.8 pad 1.68)
  other vias: 27.94,25.4
N$201  (via drill 0.8 pad 1.68)
  other vias: 27.94,27.94
N$202  (via drill 0.8 pad 1.68)
  other vias: 30.48,27.94
N$204  (via drill 0.8 pad 1.68)
  other vias: 12.7,22.86
N$205  (via drill 0.8 pad 1.68)
  other vias: 15.24,22.86
N$206  (via drill 0.8 pad 1.68)
  other vias: 17.78,22.86
N$207  (via drill 0.8 pad 1.68)
  other vias: 17.78,20.32
N$208  (via drill 0.8 pad 1.68)
  other vias: 15.24,20.32
N$209  (via drill 0.8 pad 1.68)
  other vias: 12.7,20.32
N$213  (via drill 0.8 pad 1.68)
  other vias: 17.78,25.4
N$214  (via drill 0.8 pad 1.68)
  other vias: 15.24,25.4
N$215  (via drill 0.8 pad 1.68)
  other vias: 12.7,25.4
N$216  (via drill 0.8 pad 1.68)
  other vias: 12.7,27.94
N$217  (via drill 0.8 pad 1.68)
  other vias: 15.24,27.94
N$218  (via drill 0.8 pad 1.68)
  other vias: 17.78,27.94
N$219  (via drill 0.8 pad 1.68)
  other vias: 5.08,22.86
N$220  (via drill 0.8 pad 1.68)
  other vias: 7.62,22.86
N$221  (via drill 0.8 pad 1.68)
  other vias: 10.16,22.86
N$222  (via drill 0.8 pad 1.68)
  other vias: 10.16,20.32
N$223  (via drill 0.8 pad 1.68)
  other vias: 7.62,20.32
N$224  (via drill 0.8 pad 1.68)
  other vias: 5.08,20.32
N$228  (via drill 0.8 pad 1.68)
  other vias: 10.16,25.4
N$229  (via drill 0.8 pad 1.68)
  other vias: 7.62,25.4
N$230  (via drill 0.8 pad 1.68)
  other vias: 5.08,25.4
N$231  (via drill 0.8 pad 1.68)
  other vias: 5.08,27.94
N$232  (via drill 0.8 pad 1.68)
  other vias: 7.62,27.94
N$233  (via drill 0.8 pad 1.68)
  other vias: 10.16,27.94
N$234  (via drill 0.8 pad 1.68)
  other vias: 2.54,22.86
N$235  (via drill 0.8 pad 1.68)
  other vias: 2.54,20.32
N$236  (via drill 0.8 pad 1.68)
  other vias: 90.17,13.97
N$237  (via drill 0.8 pad 1.68)
  other vias: 2.54,25.4
N$238  (via drill 0.8 pad 1.68)
  other vias: 2.54,27.94
N$239  (via drill 0.8 pad 1.68)
  other vias: 77.47,54.61
N$240  (via drill 0.8 pad 1.68)
  other vias: 80.01,54.61
N$241  (via drill 0.8 pad 1.68)
  other vias: 82.55,54.61
N$242  (via drill 0.8 pad 1.68)
  other vias: 82.55,52.07
N$243  (via drill 0.8 pad 1.68)
  other vias: 80.01,52.07
N$244  (via drill 0.8 pad 1.68)
  other vias: 77.47,52.07
N$245  (via drill 0.8 pad 1.68)
  other vias: 77.47,49.53
N$246  (via drill 0.8 pad 1.68)
  other vias: 80.01,49.53
N$247  (via drill 0.8 pad 1.68)
  other vias: 82.55,49.53
N$248  (via drill 0.8 pad 1.68)
  other vias: 82.55,57.15
N$249  (via drill 0.8 pad 1.68)
  other vias: 80.01,57.15
N$250  (via drill 0.8 pad 1.68)
  other vias: 77.47,57.15
N$251  (via drill 0.8 pad 1.68)
  other vias: 77.47,59.69
N$252  (via drill 0.8 pad 1.68)
  other vias: 80.01,59.69
N$253  (via drill 0.8 pad 1.68)
  other vias: 82.55,59.69
N$254  (via drill 0.8 pad 1.68)
  other vias: 85.09,54.61
N$255  (via drill 0.8 pad 1.68)
  other vias: 87.63,54.61
N$256  (via drill 0.8 pad 1.68)
  other vias: 90.17,54.61
N$257  (via drill 0.8 pad 1.68)
  other vias: 90.17,52.07
N$258  (via drill 0.8 pad 1.68)
  other vias: 87.63,52.07
N$259  (via drill 0.8 pad 1.68)
  other vias: 85.09,52.07
N$260  (via drill 0.8 pad 1.68)
  other vias: 85.09,49.53
N$261  (via drill 0.8 pad 1.68)
  other vias: 87.63,49.53
N$262  (via drill 0.8 pad 1.68)
  other vias: 90.17,49.53
N$263  (via drill 0.8 pad 1.68)
  other vias: 90.17,57.15
N$264  (via drill 0.8 pad 1.68)
  other vias: 87.63,57.15
N$265  (via drill 0.8 pad 1.68)
  other vias: 85.09,57.15
N$266  (via drill 0.8 pad 1.68)
  other vias: 85.09,59.69
N$267  (via drill 0.8 pad 1.68)
  other vias: 87.63,59.69
N$268  (via drill 0.8 pad 1.68)
  other vias: 90.17,59.69
N$270  (via drill 0.8 pad 1.68)
  other vias: 72.39,54.61
N$271  (via drill 0.8 pad 1.68)
  other vias: 74.93,54.61
N$272  (via drill 0.8 pad 1.68)
  other vias: 74.93,52.07
N$273  (via drill 0.8 pad 1.68)
  other vias: 72.39,52.07
N$274  (via drill 0.8 pad 1.68)
  other vias: 69.85,52.07
N$275  (via drill 0.8 pad 1.68)
  other vias: 69.85,49.53
N$276  (via drill 0.8 pad 1.68)
  other vias: 72.39,49.53
N$277  (via drill 0.8 pad 1.68)
  other vias: 74.93,49.53
N$278  (via drill 0.8 pad 1.68)
  other vias: 74.93,57.15
N$279  (via drill 0.8 pad 1.68)
  other vias: 72.39,57.15
N$281  (via drill 0.8 pad 1.68)
  other vias: 92.71,13.97
N$282  (via drill 0.8 pad 1.68)
  other vias: 95.25,13.97
N$283  (via drill 0.8 pad 1.68)
  other vias: 74.93,59.69
N$284  (via drill 0.8 pad 1.68)
  other vias: 87.63,13.97
N$285  (via drill 0.8 pad 1.68)
  other vias: 90.17,16.51
N$288  (via drill 0.8 pad 1.68)
  other vias: 90.17,19.05
N$289  (via drill 0.8 pad 1.68)
  other vias: 90.17,21.59
N$290  (via drill 0.8 pad 1.68)
  other vias: 92.71,21.59
N$291  (via drill 0.8 pad 1.68)
  other vias: 92.71,19.05
N$294  (via drill 0.8 pad 1.68)
  other vias: 72.39,59.69
N$295  (via drill 0.8 pad 1.68)
  other vias: 92.71,16.51
N$296  (via drill 0.8 pad 1.68)
  other vias: 95.25,16.51
N$297  (via drill 0.8 pad 1.68)
  other vias: 95.25,19.05
N$298  (via drill 0.8 pad 1.68)
  other vias: 95.25,21.59
N$299  (via drill 0.8 pad 1.68)
  other vias: 87.63,21.59
N$300  (via drill 0.8 pad 1.68)
  other vias: 87.63,19.05
N$301  (via drill 0.8 pad 1.68)
  other vias: 87.63,16.51
N$302  (via drill 0.8 pad 1.68)
  other vias: 92.71,24.13
N$303  (via drill 0.8 pad 1.68)
  other vias: 95.25,24.13
N$304  (via drill 0.8 pad 1.68)
  other vias: 97.79,24.13
N$305  (via drill 0.8 pad 1.68)
  other vias: 97.79,13.97
N$306  (via drill 0.8 pad 1.68)
  other vias: 90.17,39.37
N$307  (via drill 0.8 pad 1.68)
  other vias: 92.71,39.37
N$308  (via drill 0.8 pad 1.68)
  other vias: 97.79,16.51
N$309  (via drill 0.8 pad 1.68)
  other vias: 97.79,19.05
N$310  (via drill 0.8 pad 1.68)
  other vias: 97.79,21.59
N$311  (via drill 0.8 pad 1.68)
  other vias: 87.63,36.83
N$312  (via drill 0.8 pad 1.68)
  other vias: 95.25,39.37
N$313  (via drill 0.8 pad 1.68)
  other vias: 87.63,39.37
N$314  (via drill 0.8 pad 1.68)
  other vias: 90.17,36.83
N$315  (via drill 0.8 pad 1.68)
  other vias: 90.17,26.67
N$316  (via drill 0.8 pad 1.68)
  other vias: 92.71,26.67
N$317  (via drill 0.8 pad 1.68)
  other vias: 95.25,26.67
N$318  (via drill 0.8 pad 1.68)
  other vias: 85.09,39.37
N$319  (via drill 0.8 pad 1.68)
  other vias: 90.17,41.91
N$320  (via drill 0.8 pad 1.68)
  other vias: 90.17,44.45
N$321  (via drill 0.8 pad 1.68)
  other vias: 90.17,46.99
N$322  (via drill 0.8 pad 1.68)
  other vias: 92.71,46.99
N$323  (via drill 0.8 pad 1.68)
  other vias: 92.71,44.45
N$324  (via drill 0.8 pad 1.68)
  other vias: 92.71,41.91
N$325  (via drill 0.8 pad 1.68)
  other vias: 95.25,41.91
N$326  (via drill 0.8 pad 1.68)
  other vias: 95.25,44.45
N$327  (via drill 0.8 pad 1.68)
  other vias: 95.25,46.99
N$328  (via drill 0.8 pad 1.68)
  other vias: 87.63,46.99
N$329  (via drill 0.8 pad 1.68)
  other vias: 87.63,44.45
N$330  (via drill 0.8 pad 1.68)
  other vias: 87.63,41.91
N$331  (via drill 0.8 pad 1.68)
  other vias: 85.09,41.91
N$332  (via drill 0.8 pad 1.68)
  other vias: 85.09,44.45
N$333  (via drill 0.8 pad 1.68)
  other vias: 85.09,46.99
N$334  (via drill 0.8 pad 1.68)
  other vias: 87.63,26.67
N$335  (via drill 0.8 pad 1.68)
  other vias: 90.17,29.21
N$336  (via drill 0.8 pad 1.68)
  other vias: 90.17,31.75
N$337  (via drill 0.8 pad 1.68)
  other vias: 90.17,34.29
N$338  (via drill 0.8 pad 1.68)
  other vias: 92.71,34.29
N$339  (via drill 0.8 pad 1.68)
  other vias: 92.71,31.75
N$340  (via drill 0.8 pad 1.68)
  other vias: 92.71,29.21
N$341  (via drill 0.8 pad 1.68)
  other vias: 95.25,29.21
N$342  (via drill 0.8 pad 1.68)
  other vias: 95.25,31.75
N$343  (via drill 0.8 pad 1.68)
  other vias: 95.25,34.29
N$344  (via drill 0.8 pad 1.68)
  other vias: 87.63,34.29
N$345  (via drill 0.8 pad 1.68)
  other vias: 87.63,31.75
N$346  (via drill 0.8 pad 1.68)
  other vias: 87.63,29.21
N$347  (via drill 0.8 pad 1.68)
  other vias: 92.71,36.83
N$348  (via drill 0.8 pad 1.68)
  other vias: 95.25,36.83
N$349  (via drill 0.8 pad 1.68)
  other vias: 97.79,36.83
N$350  (via drill 0.8 pad 1.68)
  other vias: 97.79,26.67
N$351  (via drill 0.8 pad 1.68)
  other vias: 97.79,29.21
N$352  (via drill 0.8 pad 1.68)
  other vias: 97.79,31.75
N$353  (via drill 0.8 pad 1.68)
  other vias: 97.79,34.29
N$354  (via drill 0.8 pad 1.68)
  other vias: 5.08,58.42
N$355  (via drill 0.8 pad 1.68)
  other vias: 7.62,58.42
N$361  (via drill 0.8 pad 1.68)
  other vias: 85.09,36.83
N$364  (via drill 0.8 pad 1.68)
  other vias: 82.55,36.83
N$365  (via drill 0.8 pad 1.68)
  other vias: 7.62,60.96
N$374  (via drill 0.8 pad 1.68)
  other vias: 5.08,60.96
N$375  (via drill 0.8 pad 1.68)
  other vias: 5.08,63.5
N$376  (via drill 0.8 pad 1.68)
  other vias: 7.62,63.5
N$378  (via drill 0.8 pad 1.68)
  other vias: 2.54,58.42
N$379  (via drill 0.8 pad 1.68)
  other vias: 2.54,60.96
N$380  (via drill 0.8 pad 1.68)
  other vias: 2.54,63.5
N$381  (via drill 0.8 pad 1.68)
  other vias: 2.54,66.04
N$382  (via drill 0.8 pad 1.68)
  other vias: 5.08,66.04
N$383  (via drill 0.8 pad 1.68)
  other vias: 7.62,66.04
N$468  (via drill 0.8 pad 1.68)
  other vias: 2.54,55.88
N$473  (via drill 0.8 pad 1.68)
  other vias: 5.08,55.88
N$474  (via drill 0.8 pad 1.68)
  other vias: 7.62,55.88
N$486  (via drill 0.8 pad 1.68)
  other vias: 10.16,55.88
N$491  (via drill 0.8 pad 1.68)
  other vias: 12.7,55.88
N$492  (via drill 0.8 pad 1.68)
  other vias: 15.24,55.88
N$531  (via drill 0.8 pad 1.68)
  other vias: 92.71,57.15
N$532  (via drill 0.8 pad 1.68)
  other vias: 92.71,59.69
N$533  (via drill 0.8 pad 1.68)
  other vias: 92.71,62.23
N$534  (via drill 0.8 pad 1.68)
  other vias: 95.25,62.23
N$535  (via drill 0.8 pad 1.68)
  other vias: 95.25,59.69
N$536  (via drill 0.8 pad 1.68)
  other vias: 95.25,57.15
N$537  (via drill 0.8 pad 1.68)
  other vias: 97.79,57.15
N$538  (via drill 0.8 pad 1.68)
  other vias: 97.79,59.69
N$539  (via drill 0.8 pad 1.68)
  other vias: 97.79,62.23
N$540  (via drill 0.8 pad 1.68)
  other vias: 92.71,49.53
N$541  (via drill 0.8 pad 1.68)
  other vias: 92.71,52.07
N$542  (via drill 0.8 pad 1.68)
  other vias: 92.71,54.61
N$543  (via drill 0.8 pad 1.68)
  other vias: 95.25,54.61
N$544  (via drill 0.8 pad 1.68)
  other vias: 95.25,52.07
N$545  (via drill 0.8 pad 1.68)
  other vias: 95.25,49.53
N$546  (via drill 0.8 pad 1.68)
  other vias: 97.79,49.53
N$547  (via drill 0.8 pad 1.68)
  other vias: 97.79,52.07
N$548  (via drill 0.8 pad 1.68)
  other vias: 97.79,54.61
N$550  (via drill 0.8 pad 1.68)
  other vias: 77.47,44.45
N$551  (via drill 0.8 pad 1.68)
  other vias: 77.47,46.99
N$552  (via drill 0.8 pad 1.68)
  other vias: 80.01,46.99
N$553  (via drill 0.8 pad 1.68)
  other vias: 80.01,44.45
N$554  (via drill 0.8 pad 1.68)
  other vias: 80.01,41.91
N$555  (via drill 0.8 pad 1.68)
  other vias: 82.55,41.91
N$556  (via drill 0.8 pad 1.68)
  other vias: 82.55,44.45
N$557  (via drill 0.8 pad 1.68)
  other vias: 82.55,46.99
N$563  (via drill 0.8 pad 1.68)
  other vias: 97.79,39.37
N$566  (via drill 0.8 pad 1.68)
  other vias: 82.55,39.37
N$586  (via drill 0.8 pad 1.68)
  other vias: 35.56,55.88
N$589  (via drill 0.8 pad 1.68)
  other vias: 97.79,41.91
N$590  (via drill 0.8 pad 1.68)
  other vias: 97.79,44.45
N$595  (via drill 0.8 pad 1.68)
  other vias: 97.79,46.99
N$621  (via drill 0.8 pad 1.68)
  other vias: 74.93,46.99
N$624  (via drill 0.8 pad 1.68)
  other vias: 72.39,46.99
N$625  (via drill 0.8 pad 1.68)
  other vias: 72.39,44.45
N$627  (via drill 0.8 pad 1.68)
  other vias: 74.93,44.45
N$630  (via drill 0.8 pad 1.68)
  other vias: 69.85,44.45
N$631  (via drill 0.8 pad 1.68)
  other vias: 69.85,46.99
N$652  (via drill 0.8 pad 1.68)
  other vias: 90.17,62.23
N$653  (via drill 0.8 pad 1.68)
  other vias: 87.63,62.23
PB0  (via drill 0.8 pad 1.68)
  Bottom 0.406: IC1.14 v38.1,22.86 v35.56,22.86 v33.02,22.86
PB1  (via drill 0.7 pad 1.27, 0.8 pad 1.68)
  Top 0.406: v45.72,20.95 v53.34,20.95
  Bottom 0.406: v53.34,20.95 IC1.15 | v45.72,20.95 43.18,20.95 42.55,20.32 v38.1,20.32 v35.56,20.32 v33.02,20.32
PC0  (via drill 0.8 pad 1.68)
  Bottom 0.406: IC1.23 55.88,43.18 57.15,44.45 v62.23,44.45 v64.77,44.45 v67.31,44.45
PC1  (via drill 0.8 pad 1.68)
  Bottom 0.406: IC1.24 55.88,45.72 57.15,46.99 v62.23,46.99 v64.77,46.99 v67.31,46.99
PC2  (via drill 0.8 pad 1.68)
  Bottom 0.406: IC1.25 55.88,48.26 57.15,49.53 v62.23,49.53 v64.77,49.53 v67.31,49.53
PC3  (via drill 0.8 pad 1.68)
  Bottom 0.406: IC1.26 55.88,50.8 57.15,52.07 v62.23,52.07 v64.77,52.07 v67.31,52.07
PC4  (via drill 0.8 pad 1.68)
  Bottom 0.406: IC1.27 55.88,53.34 57.15,54.61 v62.23,54.61 v64.77,54.61 v67.31,54.61 68.58,55.88 68.58,59.69 R5.1 69.85,61.59 71.12,62.87 71.12,66.04 71.75,66.67 76.83,66.67 77.47,67.31 JP5.3
PC5  (via drill 0.8 pad 1.68)
  Bottom 0.406: IC1.28 55.88,55.88 57.15,57.15 v62.23,57.15 v64.77,57.15 v67.31,57.15 67.31,60.96 R6.1 69.85,67.31 70.48,67.94 74.3,67.94 74.93,68.58 JP5.1
PD2  (via drill 0.8 pad 1.68)
  Bottom 0.406: IC1.4 v38.1,48.26 v35.56,48.26 v33.02,48.26
PD4  (via drill 0.8 pad 1.68)
  Bottom 0.406: IC1.6 44.45,43.18 41.91,45.72 v38.1,45.72 v35.56,45.72 v33.02,45.72
PD5  (via drill 0.8 pad 1.68)
  Bottom 0.406: IC1.11 v38.1,30.48 v35.56,30.48 v33.02,30.48
PD6  (via drill 0.8 pad 1.68)
  Bottom 0.406: IC1.12 v38.1,27.94 v35.56,27.94 v33.02,27.94
PD7  (via drill 0.8 pad 1.68)
  Bottom 0.406: IC1.13 v38.1,25.4 v35.56,25.4 v33.02,25.4
R_IN
  Bottom 0.406: IC4.13 25.4,64.77 26.04,65.41 35.56,65.41 36.83,64.14 51.44,64.14 52.07,64.77 X1.3
RESET  (via drill 0.7 pad 1.27)
  Top 0.406: v60.96,22.86 v60.96,40.64
  Bottom 0.406: JP1.5 52.07,8.89 53.34,10.16 53.34,15.24 | v60.96,40.64 59.69,41.91 52.07,41.91 51.44,42.55 51.44,55.24 50.8,55.88 IC1.1 R3.1 | v60.96,22.86 IC2.17 57.15,22.86 55.56,21.27 55.56,17.46 53.34,15.24 | 53.34,15.24 53.42,15.16 S1.1
RXD  (via drill 0.8 pad 1.68)
  Bottom 0.406: IC4.12 22.86,59.69 23.5,59.05 41.91,59.05 42.55,58.42 42.55,54.61 43.81,53.34 IC1.2 46.99,53.34 47.62,52.7 47.62,50.16 46.99,49.53 43.18,49.53 41.91,50.8 v38.1,50.8 v35.56,50.8 v33.02,50.8
SCK
  Bottom 0.406: IC2.13 IC1.19 50.8,33.02 50.16,32.38 50.16,10.79 49.53,10.16 JP1.7
T_OUT
  Bottom 0.406: IC4.14 27.94,60.96 27.3,60.33 24.77,60.33 24.13,60.96 24.13,66.04 24.77,66.67 36.2,66.67 37.47,65.41 48.9,65.41 49.53,66.04 49.53,67.31 X1.2
TX0RTS  (via drill 0.8 pad 1.68)
  Bottom 0.406: IC2.4 67.94,27.94 70.48,30.48 78.11,30.48 79.38,29.21 v80.01,29.21 v82.55,29.21 v85.09,29.21
TX1RTS  (via drill 0.8 pad 1.68)
  Bottom 0.406: IC2.5 67.94,30.48 69.22,31.75 v80.01,31.75 v82.55,31.75 v85.09,31.75
TX2RTS  (via drill 0.8 pad 1.68)
  Bottom 0.406: IC2.6 78.11,33.02 79.38,34.29 v80.01,34.29 v82.55,34.29 v85.09,34.29
TXD  (via drill 0.8 pad 1.68)
  Bottom 0.406: 41.27,53.98 44.45,50.8 IC1.3 | IC4.11 20.32,58.42 20.95,57.78 40.64,57.78 41.27,57.15 41.27,53.98 | 41.27,53.98 40.64,53.34 v38.1,53.34 v35.56,53.34 v33.02,53.34

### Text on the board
tPlace: I2C | RS232 | PC5 | PC4 | TXD | PC3 | RXD | PC2 | PD2 | PC1 | PD4 | PC0 | TX2 | TX1 | PD5 | TX0 | PD6 | PD7 | PB0 | PB1 | CAN | ISP | +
